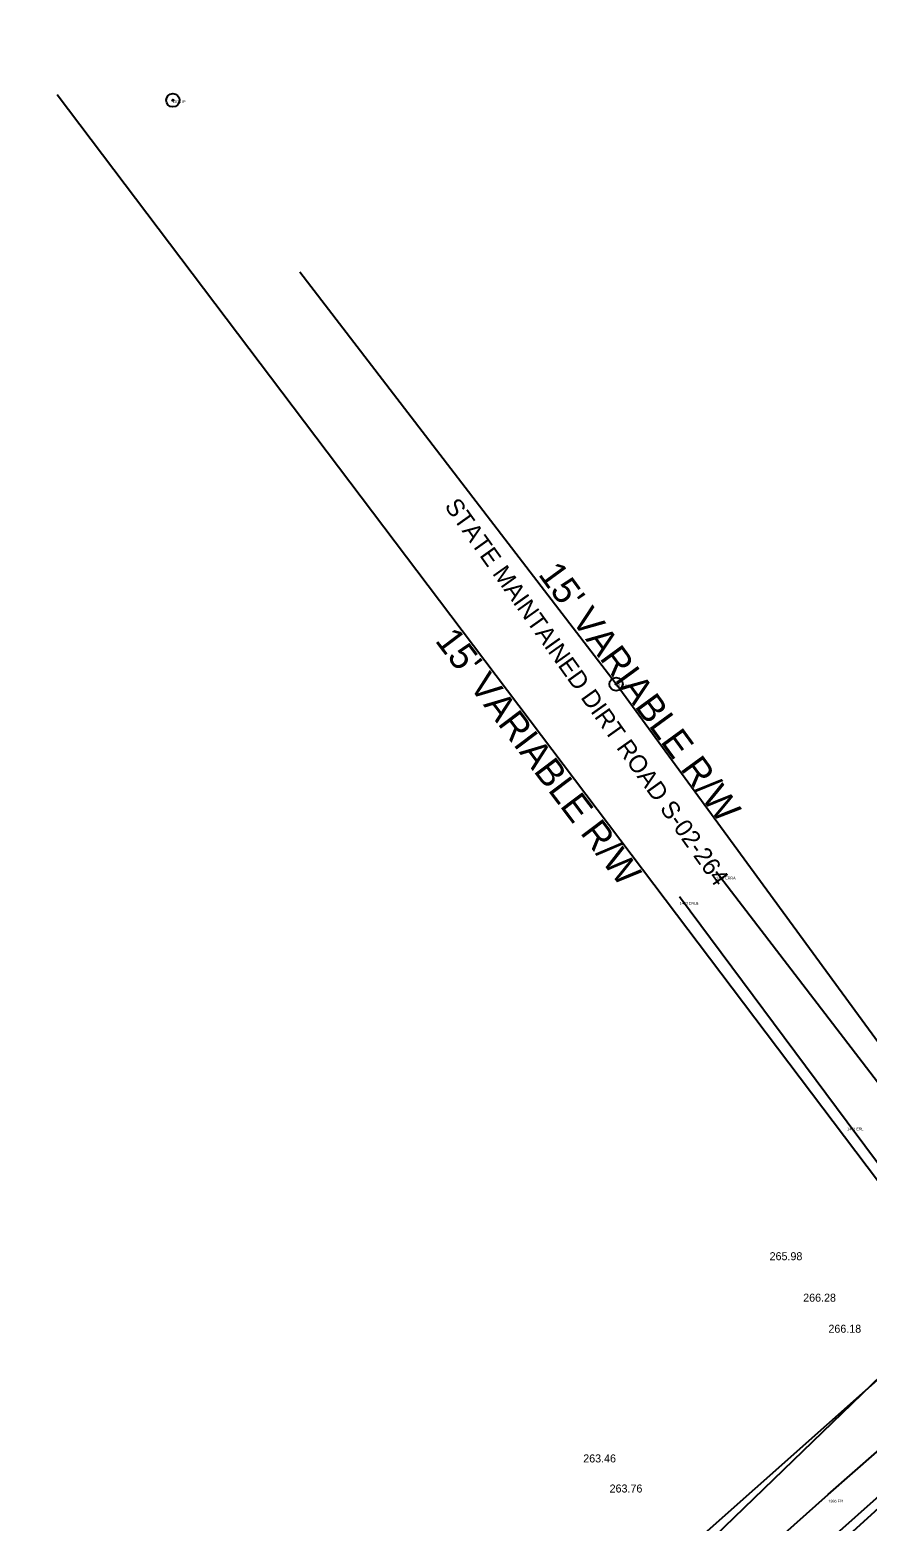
# Model space of a CAD drawing. Extents: x 49683 to 58852, y 49525 to 54803.
# Drawn here: x 54598 to 54912, y 52782 to 53341 of the extents above; entities that cross this region are included whole.
import ezdxf

# ---------------------------------------------------------------- set-up
doc = ezdxf.new("R2010")
doc.units = 0
for name, color, linetype in [('Level 1', 7, 'Continuous'), ('Level 11', 7, 'Continuous'), ('Level 12', 7, 'Continuous'), ('Level 13', 7, 'Continuous'), ('Level 18', 7, 'Continuous'), ('Level 25', 7, 'Continuous'), ('Level 3', 7, 'Continuous'), ('Level 32', 7, 'Continuous'), ('Level 53', 7, 'Continuous'), ('Level 62', 7, 'Continuous')]:
    doc.layers.add(name, color=color, linetype=linetype)

# ---------------------------------------------------------------- blocks, each defined once
blk = doc.blocks.new('IP')
at = {"layer": 'Level 12'}
for radius in [2.5, 0.25]:
    blk.add_circle((0, 0), radius, dxfattribs=at)

msp = doc.modelspace()

# ---------------------------------------------------------------- linework, layer by layer
at = {"layer": 'Level 1'}
msp.add_line((52544.81, 50683.3), (55534.58, 53340.86), dxfattribs=at)
at = {"layer": 'Level 11'}
msp.add_line((54711.21, 52637.72), (54944.99, 52863.38), dxfattribs=at)
at = {"layer": 'Level 12'}
for p, q in [((54949.37, 52864.83), (54608.23, 53316.46)), ((54817.75, 53095.57), (54699.17, 53250.03)), ((54971.79, 52884.76), (54817.75, 53095.57))]:
    msp.add_line(p, q, dxfattribs=at)
at = {"layer": 'Level 13'}
msp.add_line((54971.79, 52884.76), (53925.18, 51954.44), dxfattribs=at)
at = {"layer": 'Level 18'}
msp.add_line((54896.29, 52768.76), (54933.3, 52802.37), dxfattribs=at)
at = {"layer": 'Level 3'}
for p, q in [((54855.23, 53025.4), (54918.56, 52942.82)), ((54904.33, 52931.37), (54841.53, 53015.91)), ((54953.51, 52865.35), (54904.33, 52931.37)), ((54897.27, 52791.82), (54949.96, 52838.18)), ((54718.13, 52632.37), (54897.27, 52791.82))]:
    msp.add_line(p, q, dxfattribs=at)

# ---------------------------------------------------------------- block references
at = {"layer": 'Level 12'}
for p in [(54651.62, 53314.44), (54817.75, 53095.57)]:
    msp.add_blockref('IP', p, dxfattribs=at)

# ---------------------------------------------------------------- texts
at = {"layer": 'Level 25'}
for s, height, rotation, p in [('STATE MAINTAINED DIRT ROAD S-02-264', 6.6148, 305.4558, (54753.2, 53162.27)), ("15' VARIABLE R/W", 10, 306.157, (54788.29, 53136.73)), ("15' VARIABLE R/W", 10, 307.0661, (54749.63, 53111.85))]:
    msp.add_text(s, height=height, rotation=rotation, dxfattribs=at).set_placement(p)
at = {"layer": 'Level 32'}
for s, p in [('265.98', (54875.27, 52879.64)), ('266.28', (54887.86, 52864.1)), ('266.18', (54897.31, 52852.45)), ('263.46', (54805.42, 52803.84)), ('263.76', (54815.31, 52792.56))]:
    msp.add_text(s, height=3, dxfattribs=at).set_placement(p)
at = {"layer": 'Level 53'}
for s, p in [('1404 ERRA', (54855.23, 53022.4)), ('1403 ERLB', (54841.53, 53012.91)), ('1402 ERL', (54904.33, 52928.37)), ('1386 EPL', (54897.27, 52788.82))]:
    msp.add_text(s, height=1, dxfattribs=at).set_placement(p)
at = {"layer": 'Level 62'}
for s, p in [('1011 IP', (54651.62, 53313.44)), ('1010 IP', (54817.75, 53094.57))]:
    msp.add_text(s, height=1, dxfattribs=at).set_placement(p)

doc.saveas('drawing.dxf')
